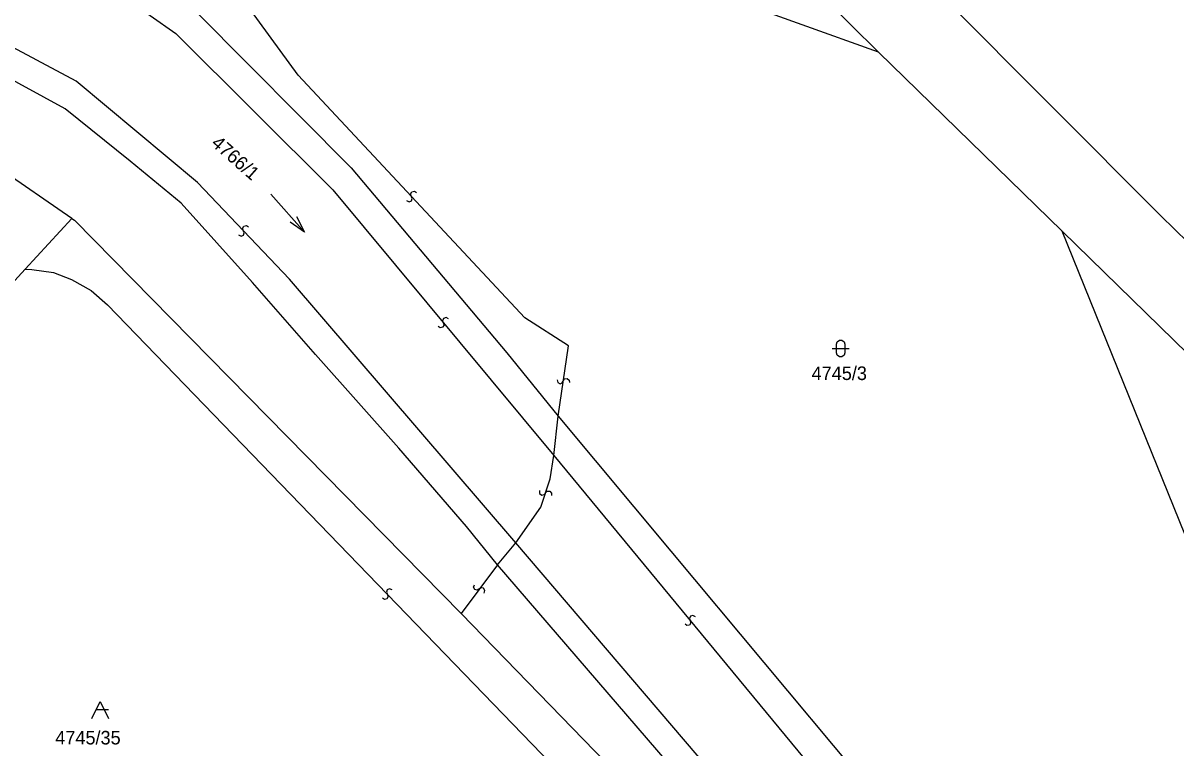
# Model space of a CAD drawing. Extents: x -266179 to -264727, y -1243225 to -1241702.
# Drawn here: x -265561 to -265424.6, y -1241875 to -1241789.3 of the extents above; entities that cross this region are included whole.
import ezdxf

# ---------------------------------------------------------------- set-up
doc = ezdxf.new("R2010")
doc.units = 0
doc.layers.add('Vrstva 1', color=7, linetype='Continuous')
doc.layers.add('Vrstva 2', color=7, linetype='Continuous')

msp = doc.modelspace()

# ---------------------------------------------------------------- linework, layer by layer
at = {"layer": 'Vrstva 1'}
for p, q in [((-265525.44, -1241727.89), (-265459.77, -1241792.75)), ((-265459.77, -1241792.75), (-265540.94, -1241763.62)), ((-265555.19, -1241812.4), (-265597.79, -1241783.22)), ((-265455.25, -1241783.13), (-265426.37, -1241812.08)), ((-265540.43, -1241788.07), (-265522.15, -1241806.42)), ((-265438.07, -1241813.93), (-265459.77, -1241792.75)), ((-265556.01, -1241799.44), (-265567.64, -1241793.12)), ((-265548.31, -1241805.63), (-265556.01, -1241799.44)), ((-265542.25, -1241810.62), (-265548.31, -1241805.63)), ((-265522.15, -1241806.42), (-265503.76, -1241828.28)), ((-265533.84, -1241819.98), (-265542.25, -1241810.62)), ((-265531.67, -1241809.544), (-265527.67, -1241814.016)), ((-265426.37, -1241812.08), (-265398.47, -1241839.67)), ((-265560.73, -1241818.42), (-265555.19, -1241812.4)), ((-265555.19, -1241812.4), (-265554.88, -1241812.62)), ((-265554.88, -1241812.62), (-265509.16, -1241859.1)), ((-265407.63, -1241843.58), (-265438.07, -1241813.93)), ((-265419.8, -1241859.01), (-265438.07, -1241813.93)), ((-265603.42, -1241864.83), (-265560.73, -1241818.42)), ((-265526.36, -1241828.5), (-265533.84, -1241819.98)), ((-265516.54, -1241839.57), (-265526.36, -1241828.5)), ((-265503.76, -1241828.28), (-265497.66, -1241835.79)), ((-265497.66, -1241835.79), (-265484.36, -1241851.74)), ((-265508.52, -1241848.82), (-265516.54, -1241839.57)), ((-265504.84, -1241853.34), (-265508.52, -1241848.82)), ((-265484.36, -1241851.74), (-265457.51, -1241883.79)), ((-265481.36, -1241880.59), (-265504.84, -1241853.34)), ((-265509.16, -1241859.1), (-265474.08, -1241895.18)), ((-265550.85, -1241870.51), (-265552.35, -1241870.51))]:
    msp.add_line(p, q, dxfattribs=at)
for points in [[(-265528.631, -1241812.192), (-265527.67, -1241814.016), (-265529.376, -1241812.859)], [(-265465.26, -1241827.78), (-265463.99, -1241827.78), (-265463.26, -1241827.78)], [(-265552.85, -1241871.51), (-265551.85, -1241869.51), (-265550.85, -1241871.51)]]:
    msp.add_lwpolyline(points, dxfattribs=at)
msp.add_lwpolyline([(-265464.76, -1241827.28), (-265464.66, -1241826.99), (-265464.41, -1241826.81), (-265464.1, -1241826.81), (-265463.85, -1241826.99), (-265463.75, -1241827.28), (-265463.75, -1241828.28), (-265463.85, -1241828.57), (-265464.1, -1241828.75), (-265464.41, -1241828.75), (-265464.66, -1241828.57), (-265464.76, -1241828.28)], close=True, dxfattribs=at)
at = {"layer": 'Vrstva 2'}
for p, q in [((-265558.47, -1241779.6), (-265542.9, -1241790.55)), ((-265528.43, -1241795.46), (-265537.72, -1241782.75)), ((-265554.68, -1241796.17), (-265564.8, -1241790.8)), ((-265542.9, -1241790.55), (-265524.32, -1241809.02)), ((-265501.61, -1241824.15), (-265528.43, -1241795.46)), ((-265540.32, -1241808.15), (-265554.68, -1241796.17)), ((-265529.47, -1241819.58), (-265540.32, -1241808.15)), ((-265524.32, -1241809.02), (-265498.2, -1241840.44)), ((-265560.73, -1241818.42), (-265559.94, -1241818.46)), ((-265559.94, -1241818.46), (-265557.36, -1241818.8)), ((-265557.36, -1241818.8), (-265555.26, -1241819.63)), ((-265555.26, -1241819.63), (-265552.92, -1241820.94)), ((-265502.7, -1241850.74), (-265529.47, -1241819.58)), ((-265552.92, -1241820.94), (-265550.98, -1241822.61)), ((-265550.98, -1241822.61), (-265484.79, -1241891.02)), ((-265496.46, -1241827.48), (-265501.61, -1241824.15)), ((-265497.66, -1241835.79), (-265496.46, -1241827.48)), ((-265498.2, -1241840.44), (-265497.66, -1241835.79)), ((-265498.61, -1241843.18), (-265498.2, -1241840.44)), ((-265498.2, -1241840.44), (-265465.91, -1241879.44)), ((-265499.74, -1241846.55), (-265498.61, -1241843.18)), ((-265502.7, -1241850.74), (-265499.74, -1241846.55)), ((-265504.84, -1241853.34), (-265502.7, -1241850.74)), ((-265479.6, -1241877.74), (-265502.7, -1241850.74)), ((-265504.84, -1241853.34), (-265509.16, -1241859.1))]:
    msp.add_line(p, q, dxfattribs=at)
for points in [[(-265515.602, -1241810.281), (-265515.31, -1241810.432), (-265515.015, -1241810.307), (-265514.929, -1241810.034), (-265515.124, -1241809.533), (-265514.973, -1241809.255), (-265514.667, -1241809.187), (-265514.438, -1241809.329)], [(-265535.473, -1241814.345), (-265535.18, -1241814.494), (-265534.887, -1241814.367), (-265534.802, -1241814.094), (-265535.001, -1241813.593), (-265534.852, -1241813.314), (-265534.546, -1241813.245), (-265534.317, -1241813.385)], [(-265510.651, -1241824.289), (-265510.934, -1241824.121), (-265511.235, -1241824.228), (-265511.338, -1241824.496), (-265511.172, -1241825.008), (-265511.339, -1241825.277), (-265511.649, -1241825.326), (-265511.869, -1241825.171)], [(-265497.795, -1241831.478), (-265497.731, -1241831.801), (-265497.45, -1241831.952), (-265497.182, -1241831.85), (-265496.912, -1241831.384), (-265496.601, -1241831.328), (-265496.357, -1241831.525), (-265496.325, -1241831.792)], [(-265499.87, -1241844.579), (-265499.864, -1241844.908), (-265499.615, -1241845.108), (-265499.334, -1241845.054), (-265498.985, -1241844.644), (-265498.669, -1241844.645), (-265498.464, -1241844.882), (-265498.48, -1241845.151)], [(-265506.43, -1241856.71), (-265506.332, -1241856.396), (-265506.506, -1241856.128), (-265506.79, -1241856.09), (-265507.25, -1241856.37), (-265507.55, -1241856.27), (-265507.67, -1241855.98), (-265507.57, -1241855.73)], [(-265517.311, -1241856.33), (-265517.606, -1241856.183), (-265517.898, -1241856.313), (-265517.98, -1241856.587), (-265517.776, -1241857.086), (-265517.923, -1241857.366), (-265518.228, -1241857.439), (-265518.459, -1241857.3)], [(-265481.445, -1241859.5), (-265481.728, -1241859.332), (-265482.029, -1241859.438), (-265482.132, -1241859.705), (-265481.968, -1241860.218), (-265482.135, -1241860.486), (-265482.445, -1241860.535), (-265482.665, -1241860.38)]]:
    msp.add_lwpolyline(points, dxfattribs=at)

# ---------------------------------------------------------------- texts
at = {"layer": 'Vrstva 1'}
msp.add_text('4766/1', height=1.6, rotation=318.62183, dxfattribs=at).set_placement((-265538.818, -1241803.688))
for s, p in [('4745/3', (-265467.693, -1241831.51)), ('4745/35', (-265557.161, -1241874.59))]:
    msp.add_text(s, height=1.6, dxfattribs=at).set_placement(p)

doc.saveas('drawing.dxf')
